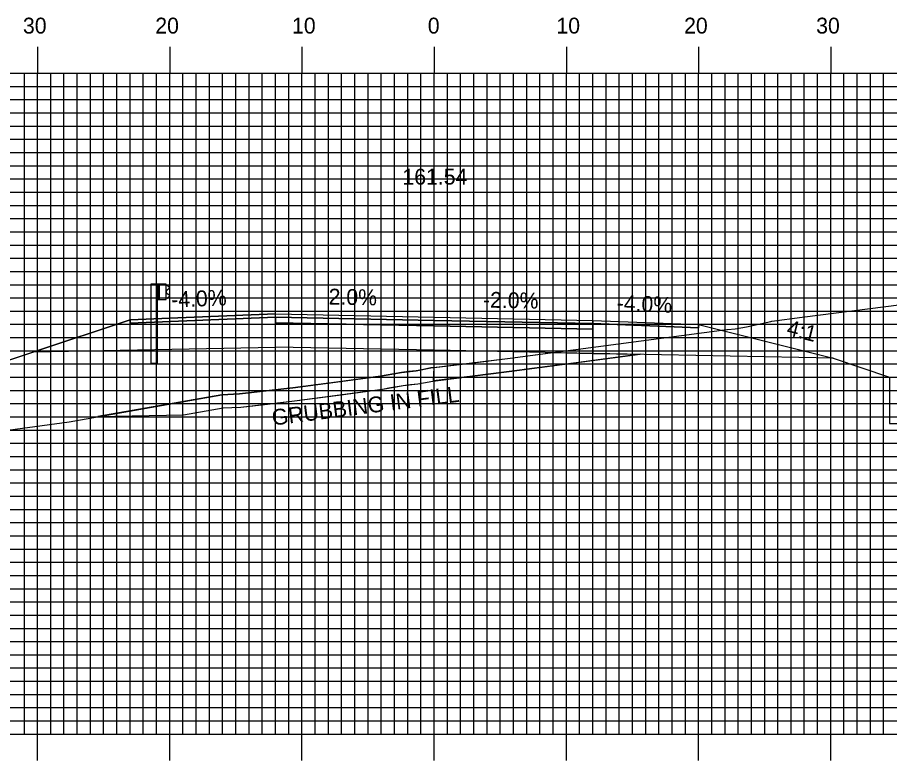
# Model space of a CAD drawing. Extents: x 1793272 to 1793615, y 442591 to 442811.
# Drawn here: x 1793406.3 to 1793472.2, y 442676.7 to 442732.9 of the extents above; entities that cross this region are included whole.
import ezdxf

# ---------------------------------------------------------------- set-up
doc = ezdxf.new("R2010")
doc.units = 0
for name, color, linetype in [('ANNOTATION', 7, 'Continuous'), ('D_Guardrail_Beam_Lt', 7, 'Continuous'), ('D_Roadway_Centerline', 7, 'Continuous'), ('D_Roadway_Centerline_Text', 7, 'Continuous'), ('D_Roadway_Edge_Shoulder', 7, 'Continuous'), ('D_Roadway_Edge_TW', 7, 'Continuous'), ('D_Roadway_FinishedGrade', 7, 'Continuous'), ('D_Roadway_Pavement', 7, 'Continuous'), ('D_Roadway_SlopeLines', 7, 'Continuous'), ('D_Roadway_SubGrade', 7, 'Continuous'), ('GRUBBING IN FILL', 7, 'Continuous'), ('H_V ANNOTATION', 7, 'Continuous'), ('MAJOR', 7, 'Continuous'), ('MINOR', 7, 'Continuous'), ('S_Roadway_Centerline', 7, 'Continuous')]:
    doc.layers.add(name, color=color, linetype=linetype)

msp = doc.modelspace()

# ---------------------------------------------------------------- linework, layer by layer
at = {"layer": 'D_Guardrail_Beam_Lt'}
for p, q in [((1793416.371, 442712.711), (1793416.371, 442706.711)), ((1793416.842, 442712.711), (1793416.371, 442712.711)), ((1793417.53, 442712.711), (1793416.842, 442712.711)), ((1793416.842, 442712.711), (1793416.842, 442711.544)), ((1793416.905, 442712.711), (1793416.905, 442711.544)), ((1793417.009, 442712.711), (1793417.009, 442711.544)), ((1793417.53, 442711.544), (1793417.53, 442712.711)), ((1793417.53, 442712.627), (1793417.604, 442712.613)), ((1793417.534, 442712.163), (1793417.534, 442712.092)), ((1793417.763, 442712.363), (1793417.568, 442712.227)), ((1793417.62, 442712.606), (1793417.763, 442712.506)), ((1793416.842, 442711.544), (1793417.53, 442711.544)), ((1793416.863, 442706.711), (1793416.863, 442711.544)), ((1793417.604, 442711.642), (1793417.53, 442711.627)), ((1793417.568, 442712.028), (1793417.763, 442711.892)), ((1793417.763, 442711.749), (1793417.62, 442711.649)), ((1793416.863, 442706.711), (1793416.371, 442706.711))]:
    msp.add_line(p, q, dxfattribs=at)
for centre, major_axis, start_param, end_param in [((1793417.613, 442712.163), (-0.0789, 0), 5.323254, 6.283185), ((1793417.613, 442712.092), (-0.0789, 0), 6.283185, 7.243116), ((1793417.596, 442712.572), (0.0417, 0), 0.959931, 1.376053), ((1793417.713, 442712.435), (0.0877, 0), 5.323254, 7.243116), ((1793417.596, 442711.683), (0.0417, 0), 4.907132, 5.323254), ((1793417.713, 442711.82), (0.0877, 0), 5.323254, 7.243116)]:
    msp.add_ellipse(centre, major_axis=major_axis, ratio=0.995501, start_param=start_param, end_param=end_param, dxfattribs=at)
at = {"layer": 'D_Roadway_Centerline'}
msp.add_lwpolyline([(1793376.377, 442697.2), (1793407.524, 442707.582), (1793414.801, 442710.007), (1793417.801, 442710.127), (1793425.801, 442710.447), (1793437.801, 442710.207), (1793449.801, 442709.967), (1793457.801, 442709.647), (1793467.975, 442707.104), (1793472.244, 442705.665)], dxfattribs=at)
at = {"layer": 'D_Roadway_Edge_Shoulder'}
for points in [[(1793425.801, 442710.447), (1793417.801, 442710.127), (1793417.801, 442710.127), (1793414.801, 442710.007), (1793414.801, 442709.757), (1793425.801, 442710.197)], [(1793449.801, 442709.967), (1793457.801, 442709.647), (1793457.801, 442709.397), (1793449.801, 442709.717)]]:
    msp.add_lwpolyline(points, close=True, dxfattribs=at)
at = {"layer": 'D_Roadway_Edge_TW'}
msp.add_lwpolyline([(1793425.801, 442710.197), (1793425.801, 442710.447), (1793437.801, 442710.207), (1793449.801, 442709.967), (1793449.801, 442709.717), (1793437.801, 442709.957)], close=True, dxfattribs=at)
at = {"layer": 'D_Roadway_FinishedGrade'}
msp.add_lwpolyline([(1793467.975, 442707.104), (1793472.244, 442705.665), (1793472.244, 442702.165), (1793517.518, 442702.165), (1793517.518, 442702.665)], dxfattribs=at)
at = {"layer": 'D_Roadway_Pavement'}
msp.add_lwpolyline([(1793425.801, 442709.781), (1793425.801, 442710.197), (1793437.801, 442709.957), (1793449.801, 442709.717), (1793449.801, 442709.301), (1793437.801, 442709.541)], close=True, dxfattribs=at)
for points in [[(1793425.801, 442710.197), (1793425.801, 442709.781)], [(1793449.801, 442709.717), (1793449.801, 442709.301)]]:
    msp.add_lwpolyline(points, dxfattribs=at)
at = {"layer": 'D_Roadway_SlopeLines'}
for points in [[(1793414.801, 442710.007), (1793376.377, 442697.2)], [(1793457.801, 442709.647), (1793467.975, 442707.104), (1793472.244, 442705.665)]]:
    msp.add_lwpolyline(points, dxfattribs=at)
at = {"layer": 'D_Roadway_SubGrade'}
for points in [[(1793425.801, 442709.781), (1793425.801, 442710.197), (1793414.801, 442709.757), (1793414.801, 442710.007), (1793407.524, 442707.582), (1793425.801, 442707.947)], [(1793425.801, 442707.947), (1793425.801, 442710.197), (1793425.801, 442709.781), (1793437.801, 442709.541), (1793449.801, 442709.301), (1793449.801, 442709.717), (1793449.801, 442707.467), (1793437.801, 442707.707)], [(1793449.801, 442709.301), (1793449.801, 442709.717), (1793457.801, 442709.397), (1793457.801, 442709.647), (1793467.975, 442707.104), (1793449.801, 442707.467)]]:
    msp.add_lwpolyline(points, close=True, dxfattribs=at)
at = {"layer": 'GRUBBING IN FILL'}
for points in [[(1793437.801, 442706.392), (1793440.553, 442706.731), (1793443.561, 442707.101), (1793446.779, 442707.528), (1793449.801, 442707.467), (1793453.387, 442707.396), (1793450.962, 442707.074), (1793448.537, 442706.752), (1793443.688, 442706.109), (1793440.692, 442705.74), (1793437.749, 442705.378)], [(1793437.801, 442706.392), (1793440.553, 442706.731), (1793443.561, 442707.101), (1793446.779, 442707.528), (1793449.801, 442707.467), (1793453.387, 442707.396), (1793450.962, 442707.074), (1793448.537, 442706.752), (1793443.688, 442706.109), (1793440.692, 442705.74), (1793437.749, 442705.378)], [(1793412.365, 442702.679), (1793418.829, 442702.808), (1793421.839, 442703.341), (1793422.502, 442703.373), (1793423.165, 442703.404), (1793425.202, 442703.637), (1793427.239, 442703.871), (1793430.57, 442704.309), (1793433.901, 442704.747), (1793434.921, 442704.945), (1793435.467, 442705.041), (1793436.021, 442705.102), (1793436.575, 442705.164), (1793437.136, 442705.268), (1793437.697, 442705.372), (1793437.801, 442705.385), (1793437.801, 442706.392), (1793437.544, 442706.361), (1793436.986, 442706.257), (1793436.428, 442706.154), (1793435.877, 442706.092), (1793435.325, 442706.031), (1793434.754, 442705.931), (1793434.183, 442705.831), (1793433.73, 442705.733), (1793430.424, 442705.298), (1793427.117, 442704.863), (1793425.101, 442704.632), (1793423.085, 442704.401), (1793421.728, 442704.337), (1793415.961, 442703.316)], [(1793412.365, 442702.679), (1793418.829, 442702.808), (1793421.839, 442703.341), (1793422.502, 442703.373), (1793423.165, 442703.404), (1793425.202, 442703.637), (1793427.239, 442703.871), (1793430.57, 442704.309), (1793433.901, 442704.747), (1793434.921, 442704.945), (1793435.467, 442705.041), (1793436.021, 442705.102), (1793436.575, 442705.164), (1793437.136, 442705.268), (1793437.697, 442705.372), (1793437.801, 442705.385), (1793437.801, 442706.392), (1793437.544, 442706.361), (1793436.986, 442706.257), (1793436.428, 442706.154), (1793435.877, 442706.092), (1793435.325, 442706.031), (1793434.754, 442705.931), (1793434.183, 442705.831), (1793433.73, 442705.733), (1793430.424, 442705.298), (1793427.117, 442704.863), (1793425.101, 442704.632), (1793423.085, 442704.401), (1793421.728, 442704.337), (1793415.961, 442703.316)]]:
    msp.add_lwpolyline(points, close=True, dxfattribs=at)
for points in [[(1793418.829, 442702.808), (1793421.839, 442703.341), (1793423.165, 442703.404), (1793427.239, 442703.871), (1793433.901, 442704.747), (1793434.374, 442704.849), (1793435.467, 442705.041), (1793436.575, 442705.164), (1793437.697, 442705.372), (1793443.688, 442706.109), (1793453.387, 442707.396)], [(1793418.829, 442702.808), (1793421.839, 442703.341), (1793423.165, 442703.404), (1793427.239, 442703.871), (1793433.901, 442704.747), (1793434.374, 442704.849), (1793435.467, 442705.041), (1793436.575, 442705.164), (1793437.697, 442705.372), (1793443.688, 442706.109), (1793453.387, 442707.396)], [(1793453.387, 442707.396), (1793450.962, 442707.074), (1793448.537, 442706.752), (1793444.615, 442706.246)], [(1793453.387, 442707.396), (1793450.962, 442707.074), (1793448.537, 442706.752), (1793444.615, 442706.246)], [(1793412.365, 442702.679), (1793418.829, 442702.808)], [(1793412.365, 442702.679), (1793418.829, 442702.808)]]:
    msp.add_lwpolyline(points, dxfattribs=at)
at = {"layer": 'MAJOR'}
for p, q in [((1793407.801, 442730.669), (1793407.801, 442728.665)), ((1793417.801, 442730.669), (1793417.801, 442728.665)), ((1793427.801, 442730.669), (1793427.801, 442728.665)), ((1793437.801, 442730.669), (1793437.801, 442728.665)), ((1793447.801, 442730.669), (1793447.801, 442728.665)), ((1793457.801, 442730.669), (1793457.801, 442728.665)), ((1793467.801, 442730.669), (1793467.801, 442728.665)), ((1793297.801, 442728.665), (1793577.801, 442728.665)), ((1793297.801, 442728.665), (1793577.801, 442728.665)), ((1793407.801, 442678.665), (1793407.801, 442728.665)), ((1793417.801, 442678.665), (1793417.801, 442728.665)), ((1793427.801, 442678.665), (1793427.801, 442728.665)), ((1793437.801, 442678.665), (1793437.801, 442728.665)), ((1793447.801, 442678.665), (1793447.801, 442728.665)), ((1793457.801, 442678.665), (1793457.801, 442728.665)), ((1793467.801, 442678.665), (1793467.801, 442728.665)), ((1793297.801, 442723.665), (1793577.801, 442723.665)), ((1793297.801, 442718.665), (1793577.801, 442718.665)), ((1793297.801, 442713.665), (1793577.801, 442713.665)), ((1793297.801, 442708.665), (1793577.801, 442708.665)), ((1793297.801, 442703.665), (1793577.801, 442703.665)), ((1793297.801, 442698.665), (1793577.801, 442698.665)), ((1793297.801, 442693.665), (1793577.801, 442693.665)), ((1793297.801, 442688.665), (1793577.801, 442688.665)), ((1793297.801, 442683.665), (1793577.801, 442683.665)), ((1793297.801, 442678.665), (1793577.801, 442678.665)), ((1793297.801, 442678.665), (1793577.801, 442678.665)), ((1793407.801, 442676.661), (1793407.801, 442678.665)), ((1793417.801, 442676.661), (1793417.801, 442678.665)), ((1793427.801, 442676.661), (1793427.801, 442678.665)), ((1793437.801, 442676.661), (1793437.801, 442678.665)), ((1793447.801, 442676.661), (1793447.801, 442678.665)), ((1793457.801, 442676.661), (1793457.801, 442678.665)), ((1793467.801, 442676.661), (1793467.801, 442678.665))]:
    msp.add_line(p, q, dxfattribs=at)
at = {"layer": 'MINOR'}
for p, q in [((1793406.801, 442678.665), (1793406.801, 442728.665)), ((1793408.801, 442678.665), (1793408.801, 442728.665)), ((1793409.801, 442678.665), (1793409.801, 442728.665)), ((1793410.801, 442678.665), (1793410.801, 442728.665)), ((1793411.801, 442678.665), (1793411.801, 442728.665)), ((1793412.801, 442678.665), (1793412.801, 442728.665)), ((1793413.801, 442678.665), (1793413.801, 442728.665)), ((1793414.801, 442678.665), (1793414.801, 442728.665)), ((1793415.801, 442678.665), (1793415.801, 442728.665)), ((1793416.801, 442678.665), (1793416.801, 442728.665)), ((1793418.801, 442678.665), (1793418.801, 442728.665)), ((1793419.801, 442678.665), (1793419.801, 442728.665)), ((1793420.801, 442678.665), (1793420.801, 442728.665)), ((1793421.801, 442678.665), (1793421.801, 442728.665)), ((1793422.801, 442678.665), (1793422.801, 442728.665)), ((1793423.801, 442678.665), (1793423.801, 442728.665)), ((1793424.801, 442678.665), (1793424.801, 442728.665)), ((1793425.801, 442678.665), (1793425.801, 442728.665)), ((1793426.801, 442678.665), (1793426.801, 442728.665)), ((1793428.801, 442678.665), (1793428.801, 442728.665)), ((1793429.801, 442678.665), (1793429.801, 442728.665)), ((1793430.801, 442678.665), (1793430.801, 442728.665)), ((1793431.801, 442678.665), (1793431.801, 442728.665)), ((1793432.801, 442678.665), (1793432.801, 442728.665)), ((1793433.801, 442678.665), (1793433.801, 442728.665)), ((1793434.801, 442678.665), (1793434.801, 442728.665)), ((1793435.801, 442678.665), (1793435.801, 442728.665)), ((1793436.801, 442678.665), (1793436.801, 442728.665)), ((1793438.801, 442678.665), (1793438.801, 442728.665)), ((1793439.801, 442678.665), (1793439.801, 442728.665)), ((1793440.801, 442678.665), (1793440.801, 442728.665)), ((1793441.801, 442678.665), (1793441.801, 442728.665)), ((1793442.801, 442678.665), (1793442.801, 442728.665)), ((1793443.801, 442678.665), (1793443.801, 442728.665)), ((1793444.801, 442678.665), (1793444.801, 442728.665)), ((1793445.801, 442678.665), (1793445.801, 442728.665)), ((1793446.801, 442678.665), (1793446.801, 442728.665)), ((1793448.801, 442678.665), (1793448.801, 442728.665)), ((1793449.801, 442678.665), (1793449.801, 442728.665)), ((1793450.801, 442678.665), (1793450.801, 442728.665)), ((1793451.801, 442678.665), (1793451.801, 442728.665)), ((1793452.801, 442678.665), (1793452.801, 442728.665)), ((1793453.801, 442678.665), (1793453.801, 442728.665)), ((1793454.801, 442678.665), (1793454.801, 442728.665)), ((1793455.801, 442678.665), (1793455.801, 442728.665)), ((1793456.801, 442678.665), (1793456.801, 442728.665)), ((1793458.801, 442678.665), (1793458.801, 442728.665)), ((1793459.801, 442678.665), (1793459.801, 442728.665)), ((1793460.801, 442678.665), (1793460.801, 442728.665)), ((1793461.801, 442678.665), (1793461.801, 442728.665)), ((1793462.801, 442678.665), (1793462.801, 442728.665)), ((1793463.801, 442678.665), (1793463.801, 442728.665)), ((1793464.801, 442678.665), (1793464.801, 442728.665)), ((1793465.801, 442678.665), (1793465.801, 442728.665)), ((1793466.801, 442678.665), (1793466.801, 442728.665)), ((1793468.801, 442678.665), (1793468.801, 442728.665)), ((1793469.801, 442678.665), (1793469.801, 442728.665)), ((1793470.801, 442678.665), (1793470.801, 442728.665)), ((1793471.801, 442678.665), (1793471.801, 442728.665)), ((1793297.801, 442727.665), (1793577.801, 442727.665)), ((1793297.801, 442726.665), (1793577.801, 442726.665)), ((1793297.801, 442725.665), (1793577.801, 442725.665)), ((1793297.801, 442724.665), (1793577.801, 442724.665)), ((1793297.801, 442722.665), (1793577.801, 442722.665)), ((1793297.801, 442721.665), (1793577.801, 442721.665)), ((1793297.801, 442720.665), (1793577.801, 442720.665)), ((1793297.801, 442719.665), (1793577.801, 442719.665)), ((1793297.801, 442717.665), (1793577.801, 442717.665)), ((1793297.801, 442716.665), (1793577.801, 442716.665)), ((1793297.801, 442715.665), (1793577.801, 442715.665)), ((1793297.801, 442714.665), (1793577.801, 442714.665)), ((1793297.801, 442712.665), (1793577.801, 442712.665)), ((1793297.801, 442711.665), (1793577.801, 442711.665)), ((1793297.801, 442710.665), (1793577.801, 442710.665)), ((1793297.801, 442709.665), (1793577.801, 442709.665)), ((1793297.801, 442707.665), (1793577.801, 442707.665)), ((1793297.801, 442706.665), (1793577.801, 442706.665)), ((1793297.801, 442705.665), (1793577.801, 442705.665)), ((1793297.801, 442704.665), (1793577.801, 442704.665)), ((1793297.801, 442702.665), (1793577.801, 442702.665)), ((1793297.801, 442701.665), (1793577.801, 442701.665)), ((1793297.801, 442700.665), (1793577.801, 442700.665)), ((1793297.801, 442699.665), (1793577.801, 442699.665)), ((1793297.801, 442697.665), (1793577.801, 442697.665)), ((1793297.801, 442696.665), (1793577.801, 442696.665)), ((1793297.801, 442695.665), (1793577.801, 442695.665)), ((1793297.801, 442694.665), (1793577.801, 442694.665)), ((1793297.801, 442692.665), (1793577.801, 442692.665)), ((1793297.801, 442691.665), (1793577.801, 442691.665)), ((1793297.801, 442690.665), (1793577.801, 442690.665)), ((1793297.801, 442689.665), (1793577.801, 442689.665)), ((1793297.801, 442687.665), (1793577.801, 442687.665)), ((1793297.801, 442686.665), (1793577.801, 442686.665)), ((1793297.801, 442685.665), (1793577.801, 442685.665)), ((1793297.801, 442684.665), (1793577.801, 442684.665)), ((1793297.801, 442682.665), (1793577.801, 442682.665)), ((1793297.801, 442681.665), (1793577.801, 442681.665)), ((1793297.801, 442680.665), (1793577.801, 442680.665)), ((1793297.801, 442679.665), (1793577.801, 442679.665))]:
    msp.add_line(p, q, dxfattribs=at)
at = {"layer": 'S_Roadway_Centerline'}
msp.add_lwpolyline([(1793399.946, 442700.901), (1793410.195, 442702.294), (1793421.728, 442704.337), (1793423.085, 442704.401), (1793427.117, 442704.863), (1793433.73, 442705.733), (1793434.183, 442705.831), (1793435.325, 442706.031), (1793436.428, 442706.154), (1793437.544, 442706.361), (1793443.561, 442707.101), (1793459.936, 442709.273), (1793459.992, 442709.274), (1793460.559, 442709.319), (1793461.421, 442709.467), (1793463.279, 442709.877), (1793463.347, 442709.895), (1793465.628, 442710.201), (1793480.673, 442712.114)], dxfattribs=at)

# ---------------------------------------------------------------- texts
at = {"layer": 'ANNOTATION'}
for s, rotation, p in [('-4.0%', 2.29061, (1793417.932, 442710.934)), ('2.0%', 358.85424, (1793429.808, 442711.168)), ('-2.0%', 358.85424, (1793441.487, 442710.934)), ('-4.0%', 357.70939, (1793451.592, 442710.697)), ('4:1', 345.96376, (1793464.393, 442708.861))]:
    msp.add_text(s, height=1.2, rotation=rotation, dxfattribs=at).set_placement(p)
at = {"layer": 'D_Roadway_Centerline'}
for s, p in [('C', (1793437.795, 442710.207)), ('L', (1793437.801, 442710.2))]:
    msp.add_text(s, height=0.0146, dxfattribs=at).set_placement(p)
at = {"layer": 'D_Roadway_Centerline_Text'}
msp.add_text('161.54', height=1.2, dxfattribs=at).set_placement((1793435.403, 442720.237))
at = {"layer": 'GRUBBING IN FILL'}
msp.add_text('GRUBBING IN FILL', height=1.2, rotation=7.28803, dxfattribs=at).set_placement((1793425.603, 442702.003))
at = {"layer": 'H_V ANNOTATION'}
for s, p in [('30', (1793406.698, 442731.665)), ('20', (1793416.708, 442731.665)), ('10', (1793427.051, 442731.665)), ('0', (1793437.319, 442731.665)), ('10', (1793447.051, 442731.665)), ('20', (1793456.708, 442731.665)), ('30', (1793466.698, 442731.665))]:
    msp.add_text(s, height=1.2, dxfattribs=at).set_placement(p)

doc.saveas('drawing.dxf')
